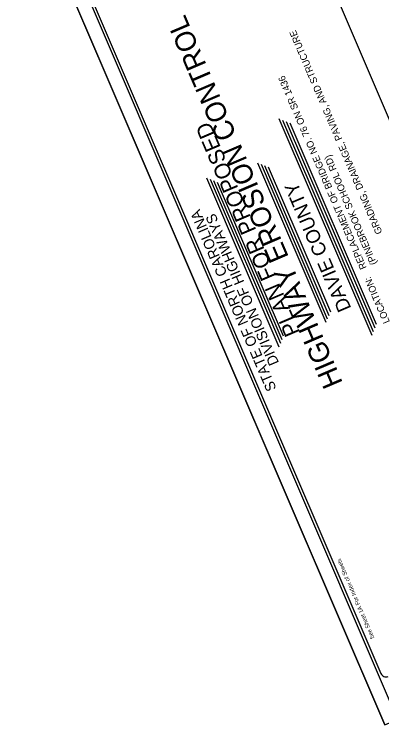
# Model space of a CAD drawing. Extents: x 1550250 to 1553148, y 808916 to 812359.
# Drawn here: x 1550250 to 1551395, y 808916 to 811132 of the extents above; entities that cross this region are included whole.
import ezdxf

# ---------------------------------------------------------------- set-up
doc = ezdxf.new("R2010")
doc.units = 0
for name, color, linetype in [('Scratch_Level_0', 7, 'Continuous'), ('Sheet_Data_Field_CELL', 7, 'Continuous'), ('Sheet_Plan_CELL', 7, 'Continuous'), ('Sheet_Title_CELL', 7, 'Continuous')]:
    doc.layers.add(name, color=color, linetype=linetype)

msp = doc.modelspace()

# ---------------------------------------------------------------- linework, layer by layer
at = {"layer": 'Scratch_Level_0'}
msp.add_line((1551404, 808916), (1550250, 811611.9), dxfattribs=at)
msp.add_lwpolyline([(1553148.4, 809662.7), (1551994.4, 812358.6), (1550250, 811611.9), (1551404, 808916)], close=True, dxfattribs=at)
at = {"layer": 'Sheet_Plan_CELL'}
msp.add_lwpolyline([(1551190.2, 811336.1), (1551800.2, 809911.1), (1552391.4, 810164.1), (1551781.4, 811589.2)], close=True, dxfattribs=at)
at = {"layer": 'Sheet_Title_CELL'}
for p, q in [((1550318.9, 811560.7), (1551421.3, 808985.4)), ((1550330.3, 811556.2), (1551391.9, 809076.1)), ((1551364.9, 810129.9), (1551075.7, 810805.5)), ((1551369.4, 810141.3), (1551087.1, 810801)), ((1551374, 810152.6), (1551098.4, 810796.4)), ((1551378.5, 810163.9), (1551109.7, 810791.9)), ((1551221.2, 810170.1), (1551008.5, 810667.1)), ((1551226, 810181), (1551019.7, 810663.1)), ((1551230.9, 810191.9), (1551031, 810659)), ((1551235.8, 810202.9), (1551042.2, 810655)), ((1551075.4, 810093.6), (1550849.5, 810621.2)), ((1551080, 810104.9), (1550860.9, 810616.7)), ((1551084.5, 810116.2), (1550872.2, 810612.2)), ((1551089.1, 810127.5), (1550883.5, 810607.6))]:
    msp.add_line(p, q, dxfattribs=at)
msp.add_arc((1551407.7, 809082.8), 17.2, 203.1736, 293.1736, dxfattribs=at)

# ---------------------------------------------------------------- texts
at = {"layer": 'Sheet_Data_Field_CELL'}
for s, height, p in [('GRADING, DRAINAGE, PAVING, AND STRUCTURE', 21.563, (1551397.2, 810451.3)), ('REPLACEMENT OF BRIDGE NO. 76 ON SR 1436', 21.563, (1551348.3, 810341.6)), ('(PINEBROOK SCHOOL RD)', 21.563, (1551380, 810355.2)), ('DAVIE COUNTY', 43.125, (1551300.5, 810215))]:
    msp.add_text(s, height=height, rotation=113.1736, dxfattribs=at).set_placement(p)
at = {"layer": 'Sheet_Title_CELL'}
for s, height, p in [('HIGHWAY EROSION CONTROL', 63.131, (1551274.2, 809982)), ('PLAN FOR PROPOSED', 49.097, (1551141.2, 810139.6)), ('STATE OF NORTH CAROLINA', 32.344, (1551067.5, 809964.4)), ('DIVISION OF HIGHWAYS', 32.344, (1551075.3, 810044.9)), ('LOCATION: ', 21.56, (1551420.5, 810172.9)), ('See Sheet 1A For Index of Sheets', 12.937, (1551372.7, 809186.2))]:
    msp.add_text(s, height=height, rotation=113.1736, dxfattribs=at).set_placement(p)

doc.saveas('drawing.dxf')
